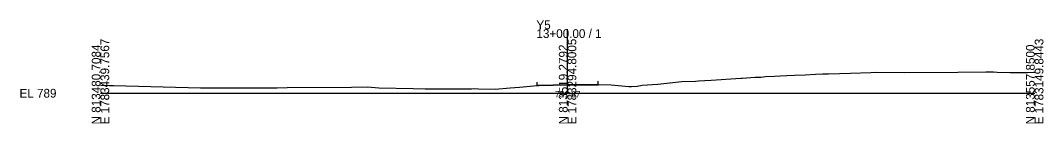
# Model space of a CAD drawing. Extents: x -26 to 1603, y -10 to 6526.
# Drawn here: x 1274.3 to 1602.8, y -9.7 to 23.3 of the extents above; entities that cross this region are included whole.
import ezdxf

# ---------------------------------------------------------------- set-up
doc = ezdxf.new("R2010")
doc.units = 0
for name, color, linetype in [('Exist Cross Section Cell', 7, 'Continuous'), ('Exist XS Center Line Elevation Label', 7, 'Continuous'), ('Exist XS Ground Line', 7, 'Continuous'), ('Prop XS EOT Tick Mark', 7, 'Continuous'), ('Prop XS Finish Grade Pavement', 7, 'Continuous')]:
    doc.layers.add(name, color=color, linetype=linetype)

msp = doc.modelspace()

# ---------------------------------------------------------------- linework, layer by layer
at = {"layer": 'Exist Cross Section Cell'}
for p, q in [((1450, 0), (1450, 20.51)), ((1300, 0), (1450, 0)), ((1450, 0), (1600, 0))]:
    msp.add_line(p, q, dxfattribs=at)
at = {"layer": 'Exist XS Ground Line'}
for p, q in [((1540.81, 6.47), (1547.36, 6.65)), ((1547.36, 6.65), (1549.31, 6.71)), ((1549.31, 6.71), (1558.33, 6.6)), ((1558.33, 6.6), (1575.3, 6.8)), ((1575.3, 6.8), (1584.31, 6.83)), ((1584.31, 6.83), (1586.76, 6.84)), ((1586.76, 6.84), (1587.93, 6.8)), ((1587.93, 6.8), (1592.08, 6.63)), ((1592.08, 6.63), (1597.72, 6.7)), ((1597.72, 6.7), (1600, 6.74)), ((1478.93, 2.92), (1486.65, 3.72)), ((1486.65, 3.72), (1491.08, 3.88)), ((1491.08, 3.88), (1492.07, 3.94)), ((1492.07, 3.94), (1496.13, 4.19)), ((1496.13, 4.19), (1505.63, 4.81)), ((1505.63, 4.81), (1506.11, 4.86)), ((1506.11, 4.86), (1510.29, 5.11)), ((1510.29, 5.11), (1512.03, 5.2)), ((1512.03, 5.2), (1513.58, 5.32)), ((1513.58, 5.32), (1516.49, 5.42)), ((1516.49, 5.42), (1518.4, 5.57)), ((1518.4, 5.57), (1520.42, 5.7)), ((1520.42, 5.7), (1522.9, 5.77)), ((1522.9, 5.77), (1526.24, 5.95)), ((1526.24, 5.95), (1529.66, 6.08)), ((1529.66, 6.08), (1531.99, 6.17)), ((1531.99, 6.17), (1533.78, 6.22)), ((1533.78, 6.22), (1540.81, 6.47)), ((1300, 2.57), (1302.88, 2.49)), ((1302.88, 2.49), (1304.22, 2.46)), ((1304.22, 2.46), (1332.14, 1.72)), ((1332.14, 1.72), (1333.06, 1.72)), ((1333.06, 1.72), (1333.39, 1.71)), ((1333.39, 1.71), (1334.63, 1.69)), ((1334.63, 1.69), (1356.79, 1.76)), ((1356.79, 1.76), (1359.94, 1.84)), ((1359.94, 1.84), (1380.61, 1.95)), ((1380.61, 1.95), (1385.73, 2.01)), ((1385.73, 2.01), (1389.35, 1.7)), ((1389.35, 1.7), (1400.43, 1.56)), ((1400.43, 1.56), (1404.23, 1.39)), ((1404.23, 1.39), (1407.92, 1.4)), ((1407.92, 1.4), (1414.31, 1.42)), ((1414.31, 1.42), (1419.15, 1.45)), ((1419.15, 1.45), (1420.24, 1.49)), ((1420.24, 1.49), (1421.34, 1.44)), ((1421.34, 1.44), (1426.76, 1.26)), ((1426.76, 1.26), (1431.58, 1.69)), ((1431.58, 1.69), (1434.61, 2)), ((1434.61, 2), (1440.23, 2.47)), ((1440.23, 2.47), (1440.74, 2.48)), ((1440.74, 2.48), (1449.96, 2.67)), ((1449.96, 2.67), (1458.49, 2.7)), ((1458.49, 2.7), (1459.85, 2.7)), ((1459.85, 2.7), (1460.33, 2.75)), ((1460.33, 2.75), (1463.99, 2.74)), ((1463.99, 2.74), (1469.67, 2.18)), ((1469.67, 2.18), (1470.51, 2.16)), ((1470.51, 2.16), (1472.32, 2.27)), ((1472.32, 2.27), (1473.91, 2.61)), ((1473.91, 2.61), (1478.93, 2.92))]:
    msp.add_line(p, q, dxfattribs=at)
at = {"layer": 'Prop XS EOT Tick Mark'}
for p, q in [((1440.23, 2.6), (1440.23, 3.6)), ((1459.86, 2.82), (1459.86, 3.82))]:
    msp.add_line(p, q, dxfattribs=at)
at = {"layer": 'Prop XS Finish Grade Pavement'}
for p, q in [((1440.23, 2.6), (1440.73, 2.61)), ((1440.73, 2.61), (1449.96, 2.8)), ((1449.96, 2.8), (1458.49, 2.82)), ((1458.49, 2.82), (1459.86, 2.82))]:
    msp.add_line(p, q, dxfattribs=at)

# ---------------------------------------------------------------- texts
at = {"layer": 'Exist Cross Section Cell'}
for s, p in [('Y5', (1440, 20.51)), ('13+00.00 / 1', (1440, 17.71)), ('EL 789', (1274, -1.4))]:
    msp.add_text(s, height=2.8, dxfattribs=at).set_placement(p)
for s, p in [('E 1783439.7567', (1302.8, -10)), ('E 1783294.8005', (1452.8, -10)), ('E 1783149.8443', (1602.8, -10)), ('N 813480.7084', (1300, -10)), ('N 813519.2792', (1450, -10)), ('N 813557.8500', (1600, -10))]:
    msp.add_text(s, height=2.8, rotation=90, dxfattribs=at).set_placement(p)
at = {"layer": 'Exist XS Center Line Elevation Label'}
msp.add_text('791.67', height=2, dxfattribs=at).set_placement((1445.94, -1.33))

doc.saveas('drawing.dxf')
